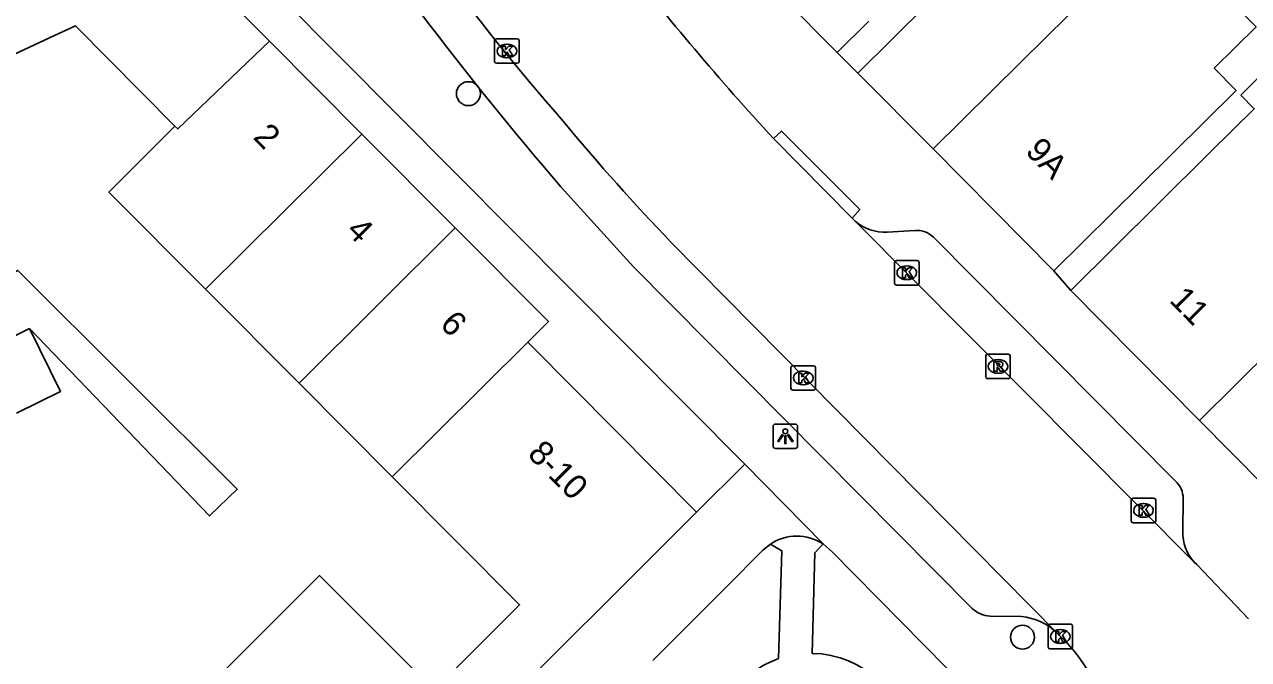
# Model space of a CAD drawing. Extents: x 160107 to 160928, y 382056 to 382918.
# Drawn here: x 160594.81 to 160644.79, y 382664.5 to 382690.42 of the extents above; entities that cross this region are included whole.
import ezdxf

# ---------------------------------------------------------------- set-up
doc = ezdxf.new("R2010")
doc.units = 0
for name, color, linetype in [('IMGEO_Boom', 7, 'Continuous'), ('IMGEO_Kolk', 7, 'Continuous'), ('IMGEO_Lichtpunt', 7, 'Continuous'), ('IMGEO_Pand', 7, 'Continuous'), ('IMGEO_Pand_nummerreeks', 7, 'Continuous'), ('IMGEO_Rijbaan_lokaal_open', 7, 'Continuous'), ('IMGEO_Rioolput', 7, 'Continuous'), ('IMGEO_Voetpad_open', 7, 'Continuous')]:
    doc.layers.add(name, color=color, linetype=linetype)

msp = doc.modelspace()

# ---------------------------------------------------------------- linework, layer by layer
at = {"layer": 'IMGEO_Boom'}
for centre in [(160612.937, 382687.595), (160635.558, 382665.411)]:
    msp.add_circle(centre, 0.489, dxfattribs=at)
at = {"layer": 'IMGEO_Kolk'}
for p, q in [((160614.008, 382688.911), (160614.008, 382689.763)), ((160614.083, 382689.837), (160614.935, 382689.837)), ((160615.009, 382689.763), (160615.009, 382688.911)), ((160614.496, 382689.617), (160614.521, 382689.617)), ((160614.935, 382688.837), (160614.083, 382688.837)), ((160614.519, 382689.057), (160614.494, 382689.057)), ((160630.337, 382679.858), (160630.337, 382680.71)), ((160630.412, 382680.784), (160631.264, 382680.784)), ((160631.338, 382680.71), (160631.338, 382679.858)), ((160630.825, 382680.564), (160630.85, 382680.564)), ((160631.264, 382679.784), (160630.412, 382679.784)), ((160630.848, 382680.004), (160630.823, 382680.004)), ((160626.106, 382675.566), (160626.106, 382676.418)), ((160626.181, 382676.492), (160627.033, 382676.492)), ((160626.594, 382676.272), (160626.619, 382676.272)), ((160627.107, 382676.418), (160627.107, 382675.566)), ((160626.617, 382675.712), (160626.592, 382675.712)), ((160627.033, 382675.492), (160626.181, 382675.492)), ((160640, 382670.159), (160640, 382671.011)), ((160640.075, 382671.085), (160640.927, 382671.085)), ((160640.488, 382670.865), (160640.513, 382670.865)), ((160641.001, 382671.011), (160641.001, 382670.159)), ((160640.511, 382670.305), (160640.486, 382670.305)), ((160640.927, 382670.085), (160640.075, 382670.085)), ((160636.603, 382665.014), (160636.603, 382665.866)), ((160636.678, 382665.94), (160637.53, 382665.94)), ((160637.091, 382665.72), (160637.116, 382665.72)), ((160637.604, 382665.866), (160637.604, 382665.014)), ((160637.53, 382664.94), (160636.678, 382664.94)), ((160637.114, 382665.16), (160637.089, 382665.16))]:
    msp.add_line(p, q, dxfattribs=at)
for points in [[(160614.008, 382688.911), (160614.008, 382689.763)], [(160614.083, 382689.837), (160614.935, 382689.837)], [(160615.009, 382689.763), (160615.009, 382688.911)], [(160614.329, 382689.537), (160614.452, 382689.537), (160614.452, 382689.386), (160614.582, 382689.537), (160614.746, 382689.537), (160614.6, 382689.386), (160614.753, 382689.137), (160614.601, 382689.137), (160614.516, 382689.301), (160614.452, 382689.234), (160614.452, 382689.137), (160614.329, 382689.137), (160614.329, 382689.537)], [(160614.935, 382688.837), (160614.083, 382688.837)], [(160630.337, 382679.858), (160630.337, 382680.71)], [(160630.412, 382680.784), (160631.264, 382680.784)], [(160631.338, 382680.71), (160631.338, 382679.858)], [(160630.658, 382680.484), (160630.781, 382680.484), (160630.781, 382680.333), (160630.911, 382680.484), (160631.075, 382680.484), (160630.929, 382680.333), (160631.082, 382680.084), (160630.93, 382680.084), (160630.845, 382680.248), (160630.781, 382680.181), (160630.781, 382680.084), (160630.658, 382680.084), (160630.658, 382680.484)], [(160631.264, 382679.784), (160630.412, 382679.784)], [(160626.106, 382675.566), (160626.106, 382676.418)], [(160626.181, 382676.492), (160627.033, 382676.492)], [(160626.427, 382676.192), (160626.55, 382676.192), (160626.55, 382676.041), (160626.68, 382676.192), (160626.844, 382676.192), (160626.698, 382676.041), (160626.851, 382675.792), (160626.699, 382675.792), (160626.614, 382675.956), (160626.55, 382675.889), (160626.55, 382675.792), (160626.427, 382675.792), (160626.427, 382676.192)], [(160627.107, 382676.418), (160627.107, 382675.566)], [(160627.033, 382675.492), (160626.181, 382675.492)], [(160640, 382670.159), (160640, 382671.011)], [(160640.075, 382671.085), (160640.927, 382671.085)], [(160640.321, 382670.785), (160640.444, 382670.785), (160640.444, 382670.634), (160640.574, 382670.785), (160640.738, 382670.785), (160640.592, 382670.634), (160640.745, 382670.385), (160640.593, 382670.385), (160640.508, 382670.549), (160640.444, 382670.482), (160640.444, 382670.385), (160640.321, 382670.385), (160640.321, 382670.785)], [(160641.001, 382671.011), (160641.001, 382670.159)], [(160640.927, 382670.085), (160640.075, 382670.085)], [(160636.603, 382665.014), (160636.603, 382665.866)], [(160636.678, 382665.94), (160637.53, 382665.94)], [(160637.604, 382665.866), (160637.604, 382665.014)], [(160636.924, 382665.64), (160637.047, 382665.64), (160637.047, 382665.489), (160637.177, 382665.64), (160637.341, 382665.64), (160637.195, 382665.489), (160637.348, 382665.24), (160637.196, 382665.24), (160637.111, 382665.404), (160637.047, 382665.337), (160637.047, 382665.24), (160636.924, 382665.24), (160636.924, 382665.64)], [(160637.53, 382664.94), (160636.678, 382664.94)]]:
    msp.add_lwpolyline(points, dxfattribs=at)
for centre, start, end in [((160614.085, 382689.761), 91.552, 178.448), ((160614.085, 382689.761), 91.552, 178.448), ((160614.933, 382689.761), 1.552, 88.448), ((160614.933, 382689.761), 1.552, 88.448), ((160614.085, 382688.913), 181.552, 268.448), ((160614.085, 382688.913), 181.552, 268.448), ((160614.933, 382688.913), 271.552, 358.448), ((160614.933, 382688.913), 271.552, 358.448), ((160630.414, 382680.708), 91.552, 178.448), ((160630.414, 382680.708), 91.552, 178.448), ((160631.262, 382680.708), 1.552, 88.448), ((160631.262, 382680.708), 1.552, 88.448), ((160630.414, 382679.86), 181.552, 268.448), ((160630.414, 382679.86), 181.552, 268.448), ((160631.262, 382679.86), 271.552, 358.448), ((160631.262, 382679.86), 271.552, 358.448), ((160626.183, 382676.416), 91.552, 178.448), ((160626.183, 382676.416), 91.552, 178.448), ((160627.031, 382676.416), 1.552, 88.448), ((160627.031, 382676.416), 1.552, 88.448), ((160626.183, 382675.568), 181.552, 268.448), ((160626.183, 382675.568), 181.552, 268.448), ((160627.031, 382675.568), 271.552, 358.448), ((160627.031, 382675.568), 271.552, 358.448), ((160640.077, 382671.009), 91.552, 178.448), ((160640.077, 382671.009), 91.552, 178.448), ((160640.925, 382671.009), 1.552, 88.448), ((160640.925, 382671.009), 1.552, 88.448), ((160640.077, 382670.161), 181.552, 268.448), ((160640.077, 382670.161), 181.552, 268.448), ((160640.925, 382670.161), 271.552, 358.448), ((160640.925, 382670.161), 271.552, 358.448), ((160636.68, 382665.864), 91.552, 178.448), ((160636.68, 382665.864), 91.552, 178.448), ((160637.528, 382665.864), 1.552, 88.448), ((160637.528, 382665.864), 1.552, 88.448), ((160636.68, 382665.016), 181.552, 268.448), ((160636.68, 382665.016), 181.552, 268.448), ((160637.528, 382665.016), 271.552, 358.448), ((160637.528, 382665.016), 271.552, 358.448)]:
    msp.add_arc(centre, 0.0765, start, end, dxfattribs=at)
for centre, major_axis, ratio, start_param, end_param in [((160614.495, 382689.337), (-0.387, 0.002), 0.722429, 4.712389, 7.853982), ((160614.52, 382689.337), (-0.39, 0.002), 0.717154, 1.570796, 4.712389), ((160630.824, 382680.284), (-0.387, 0.002), 0.722429, 4.712389, 7.853982), ((160630.849, 382680.284), (-0.39, 0.002), 0.717154, 1.570796, 4.712389), ((160626.593, 382675.992), (-0.387, 0.002), 0.722429, 4.712389, 7.853982), ((160626.618, 382675.992), (-0.39, 0.002), 0.717154, 1.570796, 4.712389), ((160640.487, 382670.585), (-0.387, 0.002), 0.722429, 4.712389, 7.853982), ((160640.512, 382670.585), (-0.39, 0.002), 0.717154, 1.570796, 4.712389), ((160637.09, 382665.44), (-0.387, 0.002), 0.722429, 4.712389, 7.853982), ((160637.115, 382665.44), (-0.39, 0.002), 0.717154, 1.570796, 4.712389)]:
    msp.add_ellipse(centre, major_axis=major_axis, ratio=ratio, start_param=start_param, end_param=end_param, dxfattribs=at)
at = {"layer": 'IMGEO_Lichtpunt'}
for p, q in [((160625.38, 382674.016), (160625.38, 382673.209)), ((160625.38, 382674.016), (160625.38, 382673.209)), ((160626.282, 382674.111), (160625.474, 382674.111)), ((160626.282, 382674.111), (160625.474, 382674.111)), ((160626.376, 382673.209), (160626.376, 382674.016)), ((160626.376, 382673.209), (160626.376, 382674.016)), ((160625.474, 382673.115), (160626.282, 382673.115)), ((160625.474, 382673.115), (160626.282, 382673.115))]:
    msp.add_line(p, q, dxfattribs=at)
for points in [[(160625.754, 382673.68), (160625.793, 382673.652), (160625.605, 382673.39), (160625.567, 382673.417), (160625.754, 382673.68)], [(160625.856, 382673.632), (160625.903, 382673.632), (160625.903, 382673.31), (160625.856, 382673.31), (160625.856, 382673.632)], [(160625.966, 382673.652), (160626.004, 382673.679), (160626.191, 382673.417), (160626.152, 382673.389), (160625.966, 382673.652)]]:
    msp.add_lwpolyline(points, dxfattribs=at)
msp.add_circle((160625.879, 382673.814), 0.0994, dxfattribs=at)
for centre, start, end in [((160625.474, 382674.016), 90, 180), ((160625.474, 382674.016), 90, 180), ((160626.282, 382674.016), 0, 90), ((160626.282, 382674.016), 0, 90), ((160625.474, 382673.209), 180, 270), ((160625.474, 382673.209), 180, 270), ((160626.282, 382673.209), 270, 0), ((160626.282, 382673.209), 270, 360)]:
    msp.add_arc(centre, 0.0946, start, end, dxfattribs=at)
at = {"layer": 'IMGEO_Pand'}
for points in [[(160588.775, 382696.517), (160592.316, 382698.153), (160594.026, 382694.335), (160598.276, 382696.305), (160604.81, 382689.741)], [(160631.913, 382685.338), (160635.505, 382688.894), (160639.354, 382692.705), (160641.065, 382694.399)], [(160641.065, 382694.399), (160645.101, 382690.323), (160643.39, 382688.629), (160644.281, 382687.729), (160640.394, 382683.88), (160636.84, 382680.362)], [(160600.953, 382686.273), (160596.902, 382690.366), (160596.045, 382689.968), (160592.551, 382688.346)], [(160600.953, 382686.273), (160601.071, 382686.154), (160604.81, 382689.741)], [(160604.81, 382689.741), (160608.586, 382685.948)], [(160637.538, 382679.564), (160641.091, 382683.083), (160643.229, 382685.208), (160645.02, 382686.982), (160644.476, 382687.532), (160645.955, 382688.998), (160650.699, 382684.208)], [(160602.2, 382679.616), (160598.259, 382683.576), (160600.953, 382686.273)], [(160608.586, 382685.948), (160602.2, 382679.616)], [(160608.586, 382685.948), (160612.397, 382682.119)], [(160636.84, 382680.362), (160631.913, 382685.338)], [(160612.397, 382682.119), (160606.023, 382675.776)], [(160612.397, 382682.119), (160616.208, 382678.291), (160615.36, 382677.448)], [(160642.792, 382674.258), (160650.219, 382681.61), (160650.485, 382681.872)], [(160606.023, 382675.776), (160602.2, 382679.616)], [(160642.792, 382674.258), (160637.538, 382679.564)], [(160593.281, 382677.154), (160595.019, 382678.008)], [(160595.019, 382678.008), (160596.281, 382675.44), (160594.487, 382674.559)], [(160609.83, 382671.951), (160615.36, 382677.448)], [(160615.36, 382677.448), (160615.508, 382677.299), (160622.246, 382670.519)], [(160606.023, 382675.776), (160609.83, 382671.951)], [(160648.047, 382668.949), (160642.792, 382674.258)], [(160609.83, 382671.951), (160615.028, 382666.729), (160611.539, 382663.245)], [(160622.246, 382670.519), (160613.22, 382661.494)], [(160602.881, 382663.95), (160606.858, 382667.926), (160611.539, 382663.245)]]:
    msp.add_lwpolyline(points, dxfattribs=at)
at = {"layer": 'IMGEO_Rijbaan_lokaal_open'}
for points in [[(160643.71, 382704.795), (160644.512, 382703.973), (160628.84, 382688.432)], [(160631.913, 382685.338), (160628.84, 382688.432)], [(160628.602, 382682.518), (160625.395, 382685.761)], [(160628.602, 382682.518), (160628.727, 382682.396)], [(160642.575, 382668.477), (160628.727, 382682.396)], [(160621.209, 382681.538), (160636.991, 382665.562)], [(160642.575, 382668.477), (160642.677, 382668.375), (160644.789, 382666.163)], [(160636.991, 382665.562), (160637.103, 382665.448)]]:
    msp.add_lwpolyline(points, dxfattribs=at)
for centre, radius, start, end in [((160692.286, 382752.48), 100.271, 210.39585, 221.23176), ((160704.293, 382758.656), 107.418, 217.54918, 222.73522), ((160681.959, 382740.126), 84.399, 219.54485, 223.96214), ((160632.95, 382660.969), 6.108, 323.4229, 47.1606)]:
    msp.add_arc(centre, radius, start, end, dxfattribs=at)
at = {"layer": 'IMGEO_Rioolput'}
for p, q in [((160634.06, 382676.037), (160634.06, 382676.889)), ((160634.135, 382676.963), (160634.987, 382676.963)), ((160634.548, 382676.743), (160634.573, 382676.743)), ((160635.061, 382676.889), (160635.061, 382676.037)), ((160634.571, 382676.183), (160634.546, 382676.183)), ((160634.987, 382675.963), (160634.135, 382675.963))]:
    msp.add_line(p, q, dxfattribs=at)
for points in [[(160634.06, 382676.037), (160634.06, 382676.889)], [(160634.135, 382676.963), (160634.987, 382676.963)], [(160635.061, 382676.889), (160635.061, 382676.037)], [(160634.649, 382676.661), (160634.397, 382676.663), (160634.397, 382676.263)], [(160634.397, 382676.263), (160634.521, 382676.263), (160634.521, 382676.425), (160634.532, 382676.425)], [(160634.575, 382676.582), (160634.521, 382676.582), (160634.521, 382676.501)], [(160634.521, 382676.501), (160634.573, 382676.501)], [(160634.579, 382676.396), (160634.65, 382676.263), (160634.79, 382676.263), (160634.725, 382676.389)], [(160634.987, 382675.963), (160634.135, 382675.963)]]:
    msp.add_lwpolyline(points, dxfattribs=at)
for centre, radius, start, end in [((160634.137, 382676.887), 0.0765, 91.552, 178.448), ((160634.137, 382676.887), 0.0765, 91.552, 178.448), ((160634.985, 382676.887), 0.0765, 1.552, 88.448), ((160634.985, 382676.887), 0.0765, 1.552, 88.448), ((160634.531, 382676.372), 0.0533, 26.0293, 88.6989), ((160634.557, 382676.69), 0.19, 274.7715, 282.9687), ((160634.581, 382676.486), 0.0964, 77.0061, 93.1865), ((160634.595, 382676.543), 0.0378, 276.6634, 79.6772), ((160634.648, 382676.551), 0.109, 350.3612, 89.416), ((160634.646, 382676.551), 0.112, 277.5842, 350.9817), ((160634.63, 382676.336), 0.108, 29.5134, 73.7905), ((160634.137, 382676.039), 0.0765, 181.552, 268.448), ((160634.137, 382676.039), 0.0765, 181.552, 268.448), ((160634.985, 382676.039), 0.0765, 271.552, 358.448), ((160634.985, 382676.039), 0.0765, 271.552, 358.448)]:
    msp.add_arc(centre, radius, start, end, dxfattribs=at)
for centre, major_axis, ratio, start_param, end_param in [((160634.547, 382676.463), (-0.387, 0.002), 0.722429, 4.712389, 7.853982), ((160634.572, 382676.463), (-0.39, 0.002), 0.717154, 1.570796, 4.712389)]:
    msp.add_ellipse(centre, major_axis=major_axis, ratio=ratio, start_param=start_param, end_param=end_param, dxfattribs=at)
at = {"layer": 'IMGEO_Voetpad_open'}
for points in [[(160627.997, 382689.28), (160614.606, 382702.76), (160611.201, 382708.753)], [(160624.229, 382672.472), (160595.859, 382700.998)], [(160629.292, 382690.557), (160627.997, 382689.28)], [(160628.84, 382688.432), (160627.997, 382689.28)], [(160625.395, 382685.761), (160625.716, 382686.067), (160628.915, 382682.861), (160628.602, 382682.518)], [(160633.509, 382666.581), (160619.68, 382680.524), (160616.712, 382683.798)], [(160630.035, 382681.936), (160631.184, 382682.015)], [(160631.926, 382681.734), (160641.796, 382671.789)], [(160595.019, 382678.008), (160602.368, 382670.363), (160603.497, 382671.449), (160594.546, 382680.379), (160593.272, 382679.797)], [(160636.84, 382680.362), (160637.538, 382679.564)], [(160624.229, 382672.472), (160622.246, 382670.519)], [(160627.418, 382669.217), (160624.229, 382672.472)], [(160642.118, 382671.059), (160642.108, 382669.73)], [(160620.462, 382664.462), (160623.48, 382667.47), (160624.964, 382668.959), (160625.269, 382669.211)], [(160625.269, 382669.211), (160625.728, 382668.939), (160625.602, 382664.538)], [(160626.97, 382664.751), (160627.081, 382668.85), (160627.418, 382669.217)], [(160627.418, 382669.217), (160627.794, 382668.892), (160636.199, 382660.37)], [(160635.52, 382666.253), (160634.238, 382666.275)]]:
    msp.add_lwpolyline(points, dxfattribs=at)
for centre, radius, start, end in [((160724.894, 382776.924), 142.744, 213.45511, 220.72293), ((160629.976, 382683.857), 1.922, 229.4856, 271.7627), ((160631.229, 382681.013), 1.003, 45.953, 92.563), ((160641.176, 382671.08), 0.942, 358.7477, 48.8564), ((160643.883, 382669.678), 1.776, 178.3227, 222.5587), ((160626.348, 382667.6), 1.939, 56.5025, 123.8175), ((160634.283, 382667.403), 1.129, 226.7251, 267.7342), ((160635.271, 382663.812), 2.454, 45.4982, 84.1784), ((160626.919, 382660.749), 4.002, 2.8449, 89.2695), ((160626.95, 382660.751), 4.019, 109.5938, 163.9591)]:
    msp.add_arc(centre, radius, start, end, dxfattribs=at)

# ---------------------------------------------------------------- texts
at = {"layer": 'IMGEO_Pand_nummerreeks'}
for s, rotation, p in [('2', 314.4142, (160604.109, 382685.787)), ('9A', 314.278, (160635.638, 382685.205)), ('4', 314.9083, (160607.906, 382681.953)), ('11', 314.7134, (160641.518, 382679.124)), ('6', 314.8509, (160611.729, 382678.135)), ('8-10', 314.8853, (160615.311, 382672.839))]:
    msp.add_text(s, height=1, rotation=rotation, dxfattribs=at).set_placement(p)

doc.saveas('drawing.dxf')
